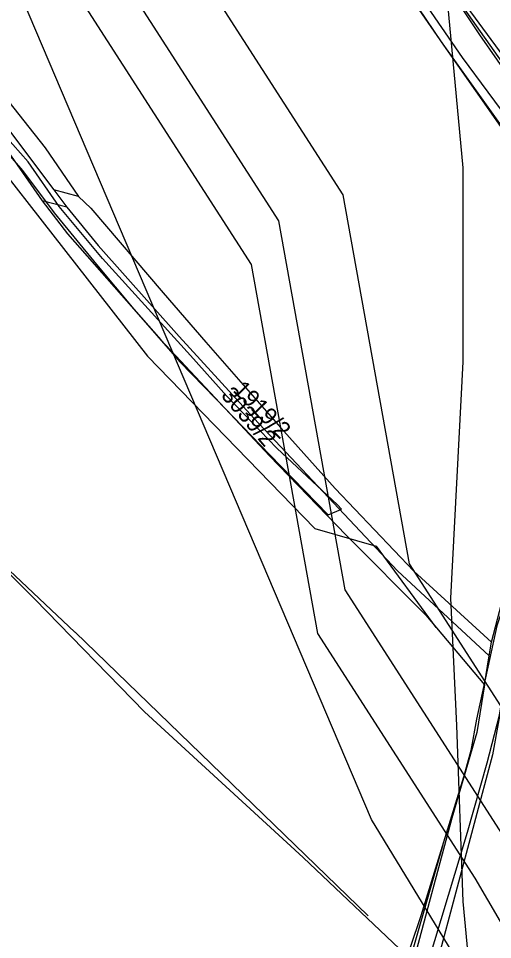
# Model space of a CAD drawing. Extents: x -564810 to -550519, y -1045831 to -1034011.
# Drawn here: x -553312 to -553168.3, y -1037817.5 to -1037538.3 of the extents above; entities that cross this region are included whole.
import ezdxf

# ---------------------------------------------------------------- set-up
doc = ezdxf.new("R2010")
doc.units = 0
for name, color, linetype in [('Interakční prvky', 7, 'Continuous'), ('KN stav', 7, 'Continuous'), ('Parcelní čísla', 7, 'Continuous'), ('Plynovod', 7, 'Continuous'), ('Polní cesty stavající', 7, 'Continuous'), ('přeložka st silnice', 7, 'Continuous'), ('STG', 7, 'Continuous'), ('Vedení VN', 7, 'Continuous'), ('Vrstva 39', 7, 'Continuous'), ('Vrstva 5', 7, 'Continuous')]:
    doc.layers.add(name, color=color, linetype=linetype)

msp = doc.modelspace()

# ---------------------------------------------------------------- linework, layer by layer
at = {"layer": 'Interakční prvky'}
for p, q in [((-553294.83, -1037724.3), (-553353.39, -1037669.26)), ((-553205.94, -1037810.26), (-553294.82, -1037724.31))]:
    msp.add_line(p, q, dxfattribs=at)
msp.add_lwpolyline([(-553417.87, -1037428.45), (-553378.32, -1037493.02), (-553379.9, -1037510.75), (-553348.58, -1037543.67), (-553272.8, -1037640.62), (-553222.18, -1037692.85), (-553203.51, -1037698.23), (-553185.48, -1037722.92)], dxfattribs=at)
msp.add_arc((-553295.52, -1037725.03), 1, 45.9579, 46.7768, dxfattribs=at)
at = {"layer": 'KN stav'}
for p, q in [((-553177.33, -1037550.15), (-553223.25, -1037483.21)), ((-553198.57, -1037504.59), (-553133.31, -1037597.17)), ((-553200.29, -1037521), (-553183.83, -1037545.36)), ((-553336.4, -1037543.51), (-553301.26, -1037590.23)), ((-553183.83, -1037545.36), (-553165.12, -1037571.51)), ((-553151.61, -1037585.09), (-553177.33, -1037550.15)), ((-553322.04, -1037554.53), (-553303.87, -1037577.45)), ((-553321.23, -1037569.96), (-553304.75, -1037593.57)), ((-553303.87, -1037577.45), (-553293.74, -1037592.29)), ((-553301.26, -1037590.23), (-553297.31, -1037595.48)), ((-553293.74, -1037592.29), (-553301.26, -1037590.23)), ((-553304.75, -1037593.57), (-553297.07, -1037603.6)), ((-553297.31, -1037595.48), (-553304.75, -1037593.57)), ((-553293.74, -1037592.29), (-553290.02, -1037595.74)), ((-553297.31, -1037595.48), (-553287.81, -1037607.08)), ((-553290.02, -1037595.74), (-553268.15, -1037621.44)), ((-553297.07, -1037603.6), (-553268.83, -1037635.66)), ((-553287.81, -1037607.08), (-553263.24, -1037634.72)), ((-553268.15, -1037621.44), (-553255.15, -1037636.35)), ((-553268.83, -1037635.66), (-553235.83, -1037670.81)), ((-553263.24, -1037634.72), (-553240.61, -1037659.45)), ((-553255.15, -1037636.35), (-553233.27, -1037661.41)), ((-553240.61, -1037659.45), (-553197.03, -1037705.75)), ((-553233.27, -1037661.41), (-553215.99, -1037680.77)), ((-553235.83, -1037670.81), (-553212.63, -1037694.9)), ((-553168.59, -1037727.36), (-553154.21, -1037671.82)), ((-553306.96, -1037714.28), (-553348.97, -1037672.71)), ((-553215.99, -1037680.77), (-553192.12, -1037705.83)), ((-553212.63, -1037694.9), (-553188.53, -1037719.12)), ((-553197.03, -1037705.75), (-553169.26, -1037731.46)), ((-553192.12, -1037705.83), (-553168.59, -1037727.36)), ((-553273.72, -1037748.46), (-553306.96, -1037714.28)), ((-553188.53, -1037719.12), (-553170.67, -1037740.22)), ((-553169.26, -1037731.46), (-553168.59, -1037727.36)), ((-553170.67, -1037740.22), (-553169.26, -1037731.46)), ((-553170.67, -1037740.22), (-553173.02, -1037754.75)), ((-553164.66, -1037741.4), (-553168.26, -1037761.53)), ((-553225.64, -1037792.57), (-553273.72, -1037748.46)), ((-553173.02, -1037754.75), (-553180.58, -1037780.65)), ((-553168.26, -1037761.53), (-553188.04, -1037835.24)), ((-553180.58, -1037780.65), (-553192.27, -1037824.2)), ((-553192.27, -1037824.2), (-553225.64, -1037792.57))]:
    msp.add_line(p, q, dxfattribs=at)
at = {"layer": 'Plynovod'}
for points in [[(-554428.56, -1035578.55), (-554428.56, -1035578.55), (-554428.56, -1035578.55), (-554027.79, -1036081.22), (-553723.76, -1036467.01), (-553550.38, -1036705.78), (-553550.38, -1036705.78), (-553522.74, -1037110.43), (-553438.57, -1037242.38), (-553213.69, -1037591.73), (-553193.58, -1037703.57), (-553145.84, -1037777.72), (-553110.67, -1037838.04), (-552972.47, -1038070.52), (-552972.47, -1038070.52), (-552302.85, -1038878.56)], [(-552322.24, -1038886.46), (-552991.86, -1038078.43), (-553130.06, -1037845.94), (-553165.24, -1037785.62), (-553212.98, -1037711.48), (-553233.08, -1037599.64), (-553457.96, -1037250.28), (-553542.14, -1037118.33), (-553569.78, -1036713.69), (-553743.15, -1036474.92), (-554047.18, -1036089.12), (-554447.95, -1035586.45)], [(-552330.5, -1038899.71), (-553000.12, -1038091.67), (-553138.32, -1037859.19), (-553173.5, -1037798.87), (-553221.24, -1037724.72), (-553241.34, -1037612.88), (-553466.22, -1037263.53), (-553550.4, -1037131.58), (-553578.03, -1036726.93), (-553751.41, -1036488.16), (-554055.44, -1036102.37), (-554456.21, -1035599.7)]]:
    msp.add_lwpolyline(points, dxfattribs=at)
at = {"layer": 'Polní cesty stavající'}
for p, q in [((-553324.74, -1037568.32), (-553310.75, -1037584.32)), ((-553309.06, -1037581.77), (-553321.89, -1037567.23)), ((-553299.6, -1037595.28), (-553309.06, -1037581.77)), ((-553310.75, -1037584.32), (-553301.18, -1037597.24)), ((-553286.53, -1037611.08), (-553299.6, -1037595.28)), ((-553301.18, -1037597.24), (-553288.33, -1037612.87)), ((-553259.83, -1037640.46), (-553286.53, -1037611.08)), ((-553288.33, -1037612.87), (-553276.96, -1037626.36)), ((-553276.96, -1037626.36), (-553263.01, -1037642.33)), ((-553248.76, -1037652.81), (-553259.83, -1037640.46)), ((-553263.01, -1037642.33), (-553252.14, -1037653.62)), ((-553233.65, -1037668.55), (-553248.76, -1037652.81)), ((-553252.14, -1037653.62), (-553235.75, -1037670.51)), ((-553215.31, -1037685.67), (-553233.65, -1037668.55)), ((-553235.75, -1037670.51), (-553218.1, -1037688.69)), ((-553214.05, -1037686.98), (-553215.31, -1037685.67)), ((-553218.1, -1037688.69), (-553214.05, -1037686.98))]:
    msp.add_line(p, q, dxfattribs=at)
at = {"layer": 'přeložka st silnice'}
msp.add_lwpolyline([(-552359.45, -1038509.27), (-552838.68, -1038201.82), (-552981.64, -1038092.23), (-553086.65, -1037975.23), (-553204.95, -1037781.11), (-553324.39, -1037500.52), (-553448.24, -1037281.74), (-553591.55, -1037076.57), (-553686.12, -1036910.24), (-553749.25, -1036695.02), (-553795.26, -1036480.46), (-553954.63, -1036164.34)], dxfattribs=at)
at = {"layer": 'STG'}
msp.add_lwpolyline([(-553189.7, -1037906.87), (-553173.54, -1037875.73), (-553173.54, -1037844.49), (-553177.21, -1037805.9), (-553179.05, -1037752.61), (-553180.89, -1037714.02), (-553177.21, -1037642.35), (-553177.21, -1037583.55), (-553184.56, -1037504.53), (-553188.23, -1037491.67), (-553201.09, -1037462.27), (-553252.53, -1037350.17), (-553318.67, -1037280.35), (-553377.46, -1037217.87), (-553419.71, -1037205), (-553438.08, -1037205)], dxfattribs=at)
at = {"layer": 'Vedení VN'}
msp.add_lwpolyline([(-553183.29, -1037788.79), (-553196.13, -1037833.53), (-553208.13, -1037865.33), (-553225.17, -1037898.98), (-553247.59, -1037929.9), (-553270.72, -1037962.16), (-553293.59, -1037992.87), (-553316.98, -1038023.5), (-553340.37, -1038054.1), (-553357.42, -1038076.87), (-553383.92, -1038097.12), (-553417.99, -1038124.02), (-553451.68, -1038150.49), (-553479.47, -1038172.23), (-553502.14, -1038190.02), (-553525.24, -1038212.86), (-553549.09, -1038287.34), (-553563.11, -1038323.58), (-553577.14, -1038354.49), (-553592.06, -1038385.26), (-553611.98, -1038408.69), (-553636.03, -1038436.08)], dxfattribs=at)
at = {"layer": 'Vrstva 39'}
for points in [[(-553196.82, -1037506.38), (-553172.2, -1037543.25), (-553145.4, -1037581.6)], [(-553154.63, -1037586.93), (-553182.33, -1037547.39), (-553198.49, -1037523.89)], [(-553138.91, -1037604.48), (-553142.84, -1037605.29), (-553149.27, -1037638.85), (-553163.01, -1037709.19), (-553165, -1037716.52), (-553166.95, -1037722.35), (-553173.09, -1037750.69), (-553174.81, -1037760.21), (-553177.03, -1037768.26), (-553189.98, -1037810.33), (-553208.86, -1037866.37), (-553218.31, -1037885.92), (-553227.05, -1037903.31), (-553231.59, -1037911.32), (-553245.44, -1037931.28), (-553253.32, -1037942), (-553269.36, -1037963.08), (-553292.72, -1037993.28), (-553316.08, -1038022.2)], [(-553189.65, -1037830.49), (-553175.87, -1037784.89), (-553169.92, -1037763.91), (-553166.15, -1037749.42), (-553164.2, -1037737.41), (-553162.4, -1037737.27), (-553162.1, -1037734.2), (-553160.87, -1037728.3), (-553159.95, -1037725.34), (-553150.56, -1037686.84), (-553149.7, -1037682.18), (-553144.39, -1037657.48), (-553143.76, -1037654.28), (-553141.35, -1037647.01), (-553138.25, -1037631.4), (-553135.44, -1037624.99), (-553131.41, -1037623.92), (-553125.58, -1037624.92), (-553129.43, -1037618.57), (-553134.92, -1037609.97), (-553138.91, -1037604.48)]]:
    msp.add_lwpolyline(points, dxfattribs=at)
at = {"layer": 'Vrstva 5'}
msp.add_lwpolyline([(-552838.62, -1037227.28), (-552866, -1037405.86), (-552870.45, -1037458.52), (-552836.04, -1037517.97), (-552862.96, -1037609.95), (-552927.56, -1037756.93), (-552962.86, -1037741.42), (-553024.92, -1037660.97), (-553063.49, -1037606.64), (-553079.67, -1037615.16), (-553096.76, -1037617.23), (-553113.85, -1037619.29), (-553224.66, -1037468.33), (-553256.7, -1037419.19), (-553309.59, -1037318.2)], dxfattribs=at)

# ---------------------------------------------------------------- texts
at = {"layer": 'Parcelní čísla'}
for s, rotation, p in [('3039/2', 310.5835, (-553250.8, -1037652.65)), ('1919/2', 314.5467, (-553247.19, -1037651.15))]:
    msp.add_text(s, height=5.1, rotation=rotation, dxfattribs=at).set_placement(p)

doc.saveas('drawing.dxf')
